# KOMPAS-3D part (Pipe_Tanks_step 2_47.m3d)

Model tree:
1. X Axis
2. Y Axis
3. Z Axis  (labels: T-Bend Dn 50; Pipe Dn 50)
     Òîëùèíà ñòåíêè 1 = 1

Referenced files in C:\Documents and Settings\kashirsky\Мои документы\Camtasia Studio\Pipelines3D\Tanks\: Tanks_step 2.a3d
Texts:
  Pipe Dn 50
  Steel ASTM A295
  Three Point Plane
  Plane at Angle
  Line and Point Plane
  Axis through Two Vertices
  Axis of Feature
  Axis of Conical Surface
  Axis through Edge
  Trim by Surface
  Trim by Sketch
  Feature with No History
  Intersection Axis of Two Planes
  Two Line Plane
  Line and Face Plane
  Bend by line
  Hole in sheet body
  Cut in sheet body
  Point in CM
  Linear Dimension from Line to Point
  Surface Finish Symbol
  Geometric Tolerance Symbol
  Leader #1
  Leader #2
  Leader #3
  Shape Deviations and Datum
  Node point number
  Mark of coordination axis
  Node point designation
  Mark/Reference designation with leader
  Mark/reference designation on line
  Mark/Reference designation without leader
  T-Bend Dn 50
  Plane of section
